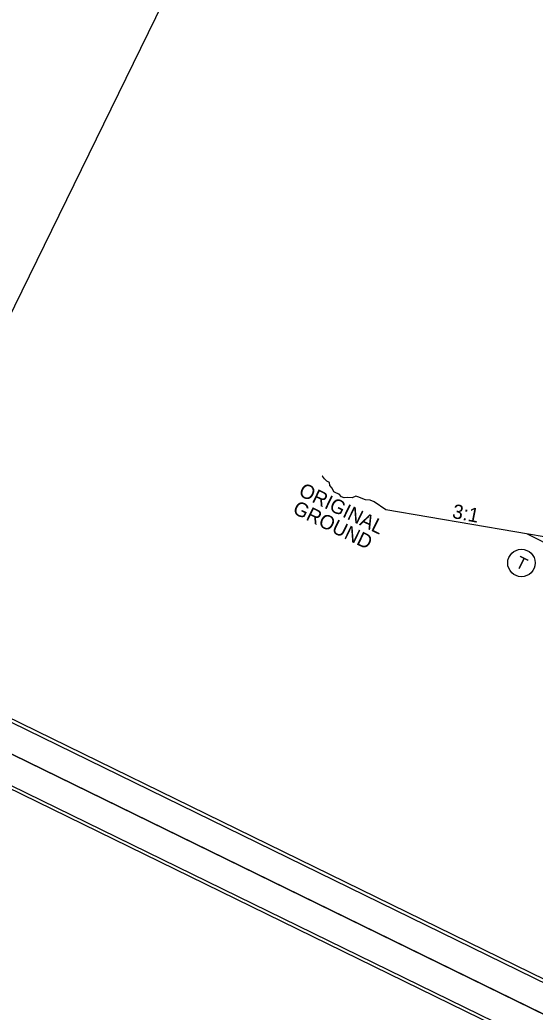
# Model space of a CAD drawing. Extents: x 1518247 to 1523638, y 635234 to 639927.
# Drawn here: x 1520253 to 1520658, y 636619 to 637399 of the extents above; entities that cross this region are included whole.
import ezdxf

# ---------------------------------------------------------------- set-up
doc = ezdxf.new("R2010")
doc.units = 0
for name, color, linetype in [('Default', 7, 'Continuous'), ('Sheet Cutting Line CELL', 7, 'Continuous'), ('Sheet Plot Border Inside CELL', 7, 'Continuous'), ('Sheet Plot Border Outside CELL', 7, 'Continuous'), ('Sheet Typical CELL', 7, 'Continuous'), ('Typical Hinge Slope Interstate CELL', 7, 'Continuous'), ('Typical ID Circle CELL', 7, 'Continuous'), ('Typical Pavement Slope CELL', 7, 'Continuous'), ('Typical Text ID Circle CELL', 7, 'Continuous')]:
    doc.layers.add(name, color=color, linetype=linetype)

msp = doc.modelspace()

# ---------------------------------------------------------------- linework, layer by layer
at = {"layer": 'Default'}
msp.add_lwpolyline([(1521471.45, 636222.33), (1519958.68, 636962.19), (1520441.97, 637950.34), (1521954.73, 637210.48)], close=True, dxfattribs=at)
at = {"layer": 'Sheet Cutting Line CELL'}
for p, q in [((1519958.68, 636962.19), (1521471.45, 636222.33)), ((1521471.45, 636222.33), (1519958.68, 636962.19))]:
    msp.add_line(p, q, dxfattribs=at)
at = {"layer": 'Sheet Plot Border Inside CELL'}
for points in [[(1521940.83, 637192.29), (1520443.78, 637924.46), (1519980.23, 636976.65), (1521477.27, 636244.48)], [(1521457.54, 636204.14), (1519960.5, 636936.31), (1519496.94, 635988.5), (1520993.99, 635256.33)]]:
    msp.add_lwpolyline(points, close=True, dxfattribs=at)
at = {"layer": 'Sheet Plot Border Outside CELL'}
for points in [[(1521954.73, 637210.48), (1520441.97, 637950.34), (1519958.68, 636962.19), (1521471.45, 636222.33)], [(1521471.45, 636222.33), (1519958.68, 636962.19), (1519475.4, 635974.04), (1520988.17, 635234.18)]]:
    msp.add_lwpolyline(points, close=True, dxfattribs=at)
at = {"layer": 'Sheet Typical CELL'}
for points in [[(1521928.48, 637195.49), (1520581, 637854.51), (1520119.69, 636911.28), (1521467.16, 636252.26)], [(1521445.2, 636207.34), (1520097.72, 636866.36), (1519636.4, 635923.13), (1520983.88, 635264.11)]]:
    msp.add_lwpolyline(points, close=True, dxfattribs=at)
at = {"layer": 'Typical Hinge Slope Interstate CELL'}
msp.add_line((1520707.01, 636985.26), (1520540.43, 637013.67), dxfattribs=at)
msp.add_lwpolyline([(1520540.43, 637013.67), (1520531.36, 637020.02), (1520528.12, 637021.32), (1520524.46, 637021.54), (1520522.3, 637022.41), (1520519.06, 637023.71), (1520516.9, 637024.57), (1520513.87, 637023.27), (1520510.2, 637023.49), (1520507.6, 637023.28), (1520505.44, 637024.14), (1520503.72, 637026.09), (1520501.56, 637026.96), (1520499.4, 637027.82), (1520498.11, 637030.85), (1520496.39, 637032.8), (1520496.17, 637035.39), (1520494.01, 637036.26), (1520492.28, 637038.2), (1520490.56, 637040.15), (1520490.46, 637040.26)], dxfattribs=at)
at = {"layer": 'Typical ID Circle CELL'}
msp.add_circle((1520647.04, 636971.98), 10.78, dxfattribs=at)
at = {"layer": 'Typical Pavement Slope CELL'}
msp.add_line((1521113.04, 636758.72), (1520651.86, 636994.66), dxfattribs=at)

# ---------------------------------------------------------------- texts
at = {"layer": 'Typical Hinge Slope Interstate CELL'}
for s, rotation, p in [('ORIGINAL', 334.0511, (1520471.11, 637025.46)), ('GROUND', 334.0511, (1520466.38, 637011.42)), ('3:1', 349.04096, (1520592.05, 637007.52))]:
    msp.add_text(s, height=11.211, rotation=rotation, dxfattribs=at).set_placement(p)
at = {"layer": 'Typical Text ID Circle CELL'}
msp.add_text('T', height=9.65, rotation=333.61889, dxfattribs=at).set_placement((1520641.63, 636969.24))

doc.saveas('drawing.dxf')
